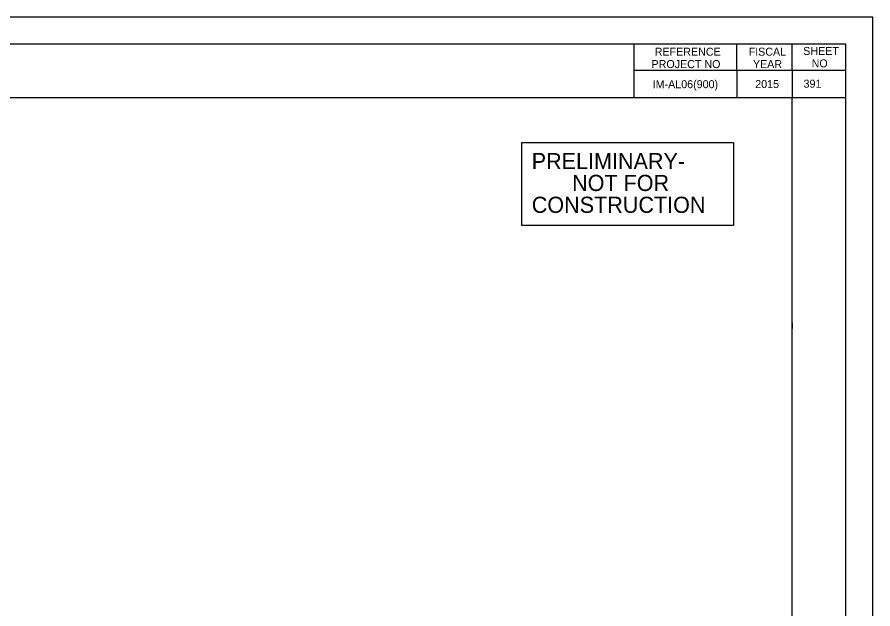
# Model space of a CAD drawing. Extents: x 1797478 to 1804836, y 246529 to 250952.
# Drawn here: x 1804676.8 to 1804836, y 250174.4 to 250284.4 of the extents above; entities that cross this region are included whole.
import ezdxf

# ---------------------------------------------------------------- set-up
doc = ezdxf.new("R2010")
doc.units = 0
for name, color, linetype in [('1', 7, 'Continuous'), ('2', 7, 'Continuous'), ('ANNO-SHT', 7, 'Continuous'), ('Level 6', 7, 'Continuous'), ('Level 62', 7, 'Continuous'), ('SHT-BDR', 7, 'Continuous'), ('SHT-BNDRY', 7, 'Continuous')]:
    doc.layers.add(name, color=color, linetype=linetype)

msp = doc.modelspace()

# ---------------------------------------------------------------- linework, layer by layer
at = {"layer": '1'}
msp.add_lwpolyline([(1804770.67, 250261.14), (1804810.07, 250261.14), (1804810.07, 250245.7), (1804770.67, 250245.7)], close=True, dxfattribs=at)
at = {"layer": '2'}
msp.add_lwpolyline([(1804820.97, 250227.57), (1804820.98, 250226.57)], dxfattribs=at)
msp.add_lwpolyline([(1804820.97, 250227.57), (1804820.98, 250226.57)], dxfattribs=at)
at = {"layer": 'Level 6'}
for p, q in [((1804791.55, 250279.42), (1804791.55, 250269.43)), ((1804810.71, 250274.42), (1804810.71, 250279.42)), ((1804821, 250274.55), (1804821, 250279.42)), ((1804831, 250274.48), (1804791.55, 250274.48)), ((1804810.71, 250274.42), (1804810.71, 250269.43)), ((1804821, 250274.55), (1804821, 250269.43)), ((1804831, 250269.43), (1804792.76, 250269.43))]:
    msp.add_line(p, q, dxfattribs=at)
at = {"layer": 'Level 62'}
msp.add_lwpolyline([(1804496, 250064.42), (1804836, 250064.42), (1804836, 250284.42), (1804496, 250284.42)], close=True, dxfattribs=at)
at = {"layer": 'SHT-BDR'}
msp.add_lwpolyline([(1804521, 250079.43), (1804821, 250079.43), (1804821, 250269.43), (1804521, 250269.43)], close=True, dxfattribs=at)
at = {"layer": 'SHT-BNDRY'}
msp.add_lwpolyline([(1804508.5, 250069.42), (1804831, 250069.42), (1804831, 250279.42), (1804508.5, 250279.42)], close=True, dxfattribs=at)

# ---------------------------------------------------------------- texts
at = {"layer": '1'}
for s, p in [('PRELIMINARY-', (1804772.53, 250256.16)), ('NOT FOR', (1804780.04, 250252.1)), ('CONSTRUCTION', (1804772.54, 250248.04))]:
    msp.add_text(s, height=3, dxfattribs=at).set_placement(p)
at = {"layer": 'ANNO-SHT'}
for s, height, p in [('IM-AL06(900)', 1.4899, (1804795.03, 250271.21)), ('2015', 1.49, (1804814.11, 250271.24)), ('  391  ', 1.49, (1804822, 250271.3))]:
    msp.add_text(s, height=height, rotation=360, dxfattribs=at).set_placement(p)
at = {"layer": 'Level 6'}
for s, p in [('REFERENCE', (1804795.42, 250277.25)), ('FISCAL', (1804812.89, 250277.25)), ('SHEET', (1804823.04, 250277.39)), ('PROJECT NO', (1804794.82, 250274.95)), ('YEAR', (1804813.69, 250274.95)), ('NO', (1804824.61, 250275.09))]:
    msp.add_text(s, height=1.488, dxfattribs=at).set_placement(p)

doc.saveas('drawing.dxf')
